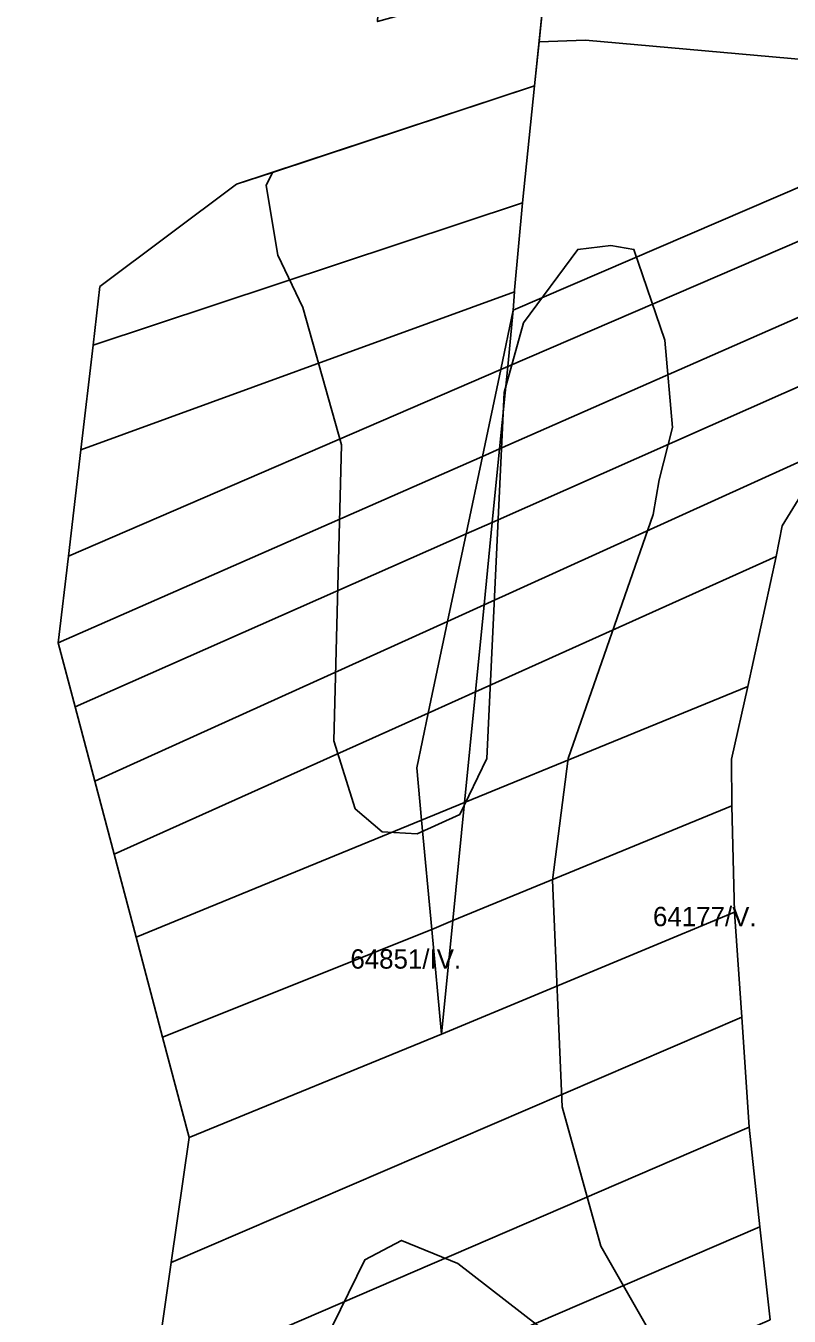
# Model space of a CAD drawing. Extents: x -521261 to -517465, y -1182764 to -1179456.
# Drawn here: x -520761.1 to -520563.9, y -1181487.6 to -1181154.3 of the extents above; entities that cross this region are included whole.
import ezdxf

# ---------------------------------------------------------------- set-up
doc = ezdxf.new("R2010")
doc.units = 0
for name, color, linetype in [('95560013', 7, 'Continuous'), ('95610013', 7, 'Continuous'), ('95620013', 7, 'Continuous'), ('95660013', 7, 'Continuous')]:
    doc.layers.add(name, color=color, linetype=linetype)

msp = doc.modelspace()

# ---------------------------------------------------------------- linework, layer by layer
at = {"layer": '95560013'}
for points in [[(-520499.14, -1181174.37), (-520506.5, -1181186.19), (-520636.58, -1181242.29), (-520635.15, -1181227.75), (-520521.72, -1181178.92)], [(-520506.5, -1181186.19), (-520522.96, -1181212.61), (-520638.68, -1181263.52), (-520636.58, -1181242.29)], [(-520522.96, -1181212.61), (-520537.12, -1181236.65), (-520640.57, -1181282.52), (-520638.68, -1181263.52)], [(-520635.15, -1181227.75), (-520636.58, -1181242.29), (-520638.38, -1181243.06)], [(-520537.12, -1181236.65), (-520553.33, -1181263.31), (-520642.68, -1181303.81), (-520640.57, -1181282.52)], [(-520638.38, -1181243.06), (-520636.58, -1181242.29), (-520638.68, -1181263.52), (-520643.12, -1181265.47)], [(-520643.12, -1181265.47), (-520638.68, -1181263.52), (-520640.57, -1181282.52), (-520647.35, -1181285.51)], [(-520553.33, -1181263.31), (-520565.67, -1181283.42), (-520567.22, -1181291.34), (-520644.91, -1181326.28), (-520642.68, -1181303.81)], [(-520647.35, -1181285.51), (-520640.57, -1181282.52), (-520642.68, -1181303.81), (-520652.13, -1181308.1)], [(-520567.22, -1181291.34), (-520574.59, -1181324.96), (-520647.74, -1181354.91), (-520644.91, -1181326.28)], [(-520652.13, -1181308.1), (-520642.68, -1181303.81), (-520644.91, -1181326.28), (-520657.13, -1181331.78)], [(-520657.13, -1181331.78), (-520644.91, -1181326.28), (-520647.74, -1181354.91), (-520658.84, -1181359.45), (-520660.11, -1181345.91)], [(-520574.59, -1181324.96), (-520578.82, -1181343.7), (-520578.73, -1181355.74), (-520650.81, -1181385.36), (-520647.74, -1181354.91)], [(-520658.84, -1181359.45), (-520647.74, -1181354.91), (-520650.81, -1181385.36), (-520656.21, -1181387.66)], [(-520578.73, -1181355.74), (-520577.99, -1181383.26), (-520653.67, -1181414.77), (-520650.81, -1181385.36)], [(-520577.99, -1181383.26), (-520576.08, -1181410.39), (-520723.52, -1181473.69), (-520718.89, -1181441.47), (-520653.67, -1181414.77)], [(-520656.21, -1181387.66), (-520650.81, -1181385.36), (-520653.67, -1181414.77)], [(-520576.08, -1181410.39), (-520574.24, -1181438.77), (-520728.04, -1181505.07), (-520723.52, -1181473.69)], [(-520574.24, -1181438.77), (-520571.45, -1181464.53), (-520732.41, -1181533.87), (-520728.04, -1181505.07)], [(-520571.45, -1181464.53), (-520568.81, -1181488.5), (-520615.8, -1181509), (-520733.75, -1181560.43), (-520736.16, -1181561.46), (-520732.41, -1181533.87)]]:
    msp.add_lwpolyline(points, close=True, dxfattribs=at)
at = {"layer": '95610013'}
for points in [[(-520501.61, -1181108.38), (-520522.92, -1181119.2), (-520521.72, -1181178.92), (-520635.15, -1181227.75), (-520634.86, -1181222.95), (-520634.84, -1181222.55), (-520632.77, -1181200.01), (-520629.67, -1181169.79), (-520626.5, -1181138.86), (-520614.85, -1181131.39), (-520585.05, -1181120.87), (-520571.69, -1181120.15), (-520556.17, -1181117.12), (-520527.54, -1181106.61)], [(-520706.63, -1181195.17), (-520629.67, -1181169.79), (-520632.77, -1181200.01), (-520743.69, -1181236.73), (-520741.92, -1181221.6)], [(-520632.77, -1181200.01), (-520634.84, -1181222.55), (-520634.86, -1181222.95), (-520746.87, -1181263.8), (-520743.69, -1181236.73)], [(-520634.86, -1181222.95), (-520635.15, -1181227.75), (-520638.38, -1181243.06), (-520750.08, -1181291.23), (-520746.87, -1181263.8)], [(-520638.38, -1181243.06), (-520643.12, -1181265.47), (-520752.71, -1181313.69), (-520750.08, -1181291.23)], [(-520643.12, -1181265.47), (-520647.35, -1181285.51), (-520748.34, -1181330.19), (-520752.71, -1181313.69)], [(-520647.35, -1181285.51), (-520652.13, -1181308.1), (-520743.26, -1181349.41), (-520748.34, -1181330.19)], [(-520652.13, -1181308.1), (-520657.13, -1181331.78), (-520738.26, -1181368.28), (-520743.26, -1181349.41)], [(-520657.13, -1181331.78), (-520660.11, -1181345.91), (-520658.84, -1181359.45), (-520732.6, -1181389.64), (-520738.26, -1181368.28)], [(-520656.21, -1181387.66), (-520725.79, -1181415.51), (-520732.6, -1181389.64), (-520658.84, -1181359.45)], [(-520653.67, -1181414.77), (-520718.89, -1181441.47), (-520725.79, -1181415.51), (-520656.21, -1181387.66)]]:
    msp.add_lwpolyline(points, close=True, dxfattribs=at)
at = {"layer": '95620013'}
for points in [[(-520769.1, -1181131.19), (-520745.59, -1181130), (-520727.31, -1181126.94), (-520725.36, -1181151.77), (-520669.91, -1181146.41), (-520670.21, -1181153.14), (-520645.15, -1181146.15), (-520638.52, -1181144.14), (-520626.5, -1181138.86), (-520629.67, -1181169.79), (-520706.63, -1181195.17), (-520741.92, -1181221.6), (-520743.69, -1181236.73), (-520746.87, -1181263.8), (-520750.08, -1181291.23), (-520752.71, -1181313.69), (-520748.34, -1181330.19), (-520743.26, -1181349.41), (-520738.26, -1181368.28), (-520732.6, -1181389.64), (-520725.79, -1181415.51), (-520718.89, -1181441.47), (-520723.52, -1181473.69), (-520728.04, -1181505.07)], [(-520568.81, -1181488.5), (-520571.45, -1181464.53), (-520574.24, -1181438.77), (-520576.08, -1181410.39), (-520577.99, -1181383.26), (-520578.73, -1181355.74), (-520578.82, -1181343.7), (-520574.59, -1181324.96), (-520567.22, -1181291.34), (-520565.67, -1181283.42), (-520553.33, -1181263.31)]]:
    msp.add_lwpolyline(points, dxfattribs=at)
at = {"layer": '95660013'}
for points in [[(-520522.92, -1181119.2), (-520522.19, -1181155.36), (-520524.5, -1181155.5), (-520559.5, -1181163), (-520616.5, -1181158), (-520628.5, -1181158.39), (-520626.5, -1181138.86)], [(-520568.81, -1181488.5), (-520571.45, -1181464.53), (-520574.24, -1181438.77), (-520576.08, -1181410.39), (-520577.99, -1181383.26), (-520578.73, -1181355.74), (-520578.82, -1181343.7), (-520574.59, -1181324.96), (-520567.22, -1181291.34), (-520565.67, -1181283.42), (-520553.33, -1181263.31), (-520537.12, -1181236.65), (-520522.96, -1181212.61), (-520506.5, -1181186.19), (-520499.14, -1181174.37), (-520521.72, -1181178.92), (-520522.19, -1181155.36), (-520522.92, -1181119.2)], [(-520626.5, -1181138.86), (-520628.5, -1181158.39), (-520629.67, -1181169.79), (-520697.37, -1181192.11), (-520706.63, -1181195.17), (-520741.92, -1181221.6), (-520743.69, -1181236.73), (-520746.87, -1181263.8), (-520750.08, -1181291.23), (-520752.71, -1181313.69), (-520748.34, -1181330.19), (-520743.26, -1181349.41), (-520738.26, -1181368.28), (-520732.6, -1181389.64), (-520725.79, -1181415.51), (-520718.89, -1181441.47), (-520723.52, -1181473.69), (-520728.04, -1181505.07)], [(-520578.5, -1181529), (-520612.5, -1181469.5), (-520622.5, -1181433.5), (-520625, -1181375), (-520621, -1181343.5), (-520599, -1181280.5), (-520597.5, -1181271.5), (-520594, -1181258), (-520596, -1181235.5), (-520604, -1181212), (-520610, -1181211), (-520618.5, -1181212), (-520632.5, -1181231), (-520637.5, -1181249), (-520642, -1181343.5), (-520649, -1181358), (-520660, -1181363), (-520669, -1181362.5), (-520676, -1181356.5), (-520681.5, -1181339), (-520679.5, -1181262.5), (-520689.5, -1181227), (-520696, -1181213.5), (-520699, -1181195.5), (-520697.37, -1181192.11), (-520629.67, -1181169.79), (-520628.5, -1181158.39), (-520616.5, -1181158), (-520559.5, -1181163)], [(-520728.04, -1181505.07), (-520723.52, -1181473.69), (-520718.89, -1181441.47), (-520725.79, -1181415.51), (-520732.6, -1181389.64), (-520738.26, -1181368.28), (-520743.26, -1181349.41), (-520748.34, -1181330.19), (-520752.71, -1181313.69), (-520750.08, -1181291.23), (-520746.87, -1181263.8), (-520743.69, -1181236.73), (-520741.92, -1181221.6), (-520706.63, -1181195.17), (-520697.37, -1181192.11), (-520699, -1181195.5), (-520696, -1181213.5), (-520689.5, -1181227), (-520679.5, -1181262.5), (-520681.5, -1181339), (-520676, -1181356.5), (-520669, -1181362.5), (-520660, -1181363), (-520649, -1181358), (-520642, -1181343.5), (-520637.5, -1181249), (-520632.5, -1181231), (-520618.5, -1181212), (-520610, -1181211), (-520604, -1181212), (-520596, -1181235.5), (-520594, -1181258), (-520597.5, -1181271.5), (-520599, -1181280.5), (-520621, -1181343.5), (-520625, -1181375), (-520622.5, -1181433.5), (-520612.5, -1181469.5), (-520578.5, -1181529), (-520649.5, -1181474), (-520664, -1181468), (-520673.5, -1181473), (-520684, -1181494.5)], [(-520553.33, -1181263.31), (-520565.67, -1181283.42), (-520567.22, -1181291.34), (-520574.59, -1181324.96), (-520578.82, -1181343.7), (-520578.73, -1181355.74), (-520577.99, -1181383.26), (-520576.08, -1181410.39), (-520574.24, -1181438.77), (-520571.45, -1181464.53), (-520568.81, -1181488.5)], [(-520684, -1181494.5), (-520673.5, -1181473), (-520664, -1181468), (-520649.5, -1181474), (-520578.5, -1181529)]]:
    msp.add_lwpolyline(points, dxfattribs=at)

# ---------------------------------------------------------------- texts
for s, rotation, p in [('64177/V.', 360, (-520599.07, -1181386.85)), ('64851/IV.', 0, (-520677.24, -1181397.81))]:
    msp.add_text(s, height=5, rotation=rotation, dxfattribs=at).set_placement(p)

doc.saveas('drawing.dxf')
